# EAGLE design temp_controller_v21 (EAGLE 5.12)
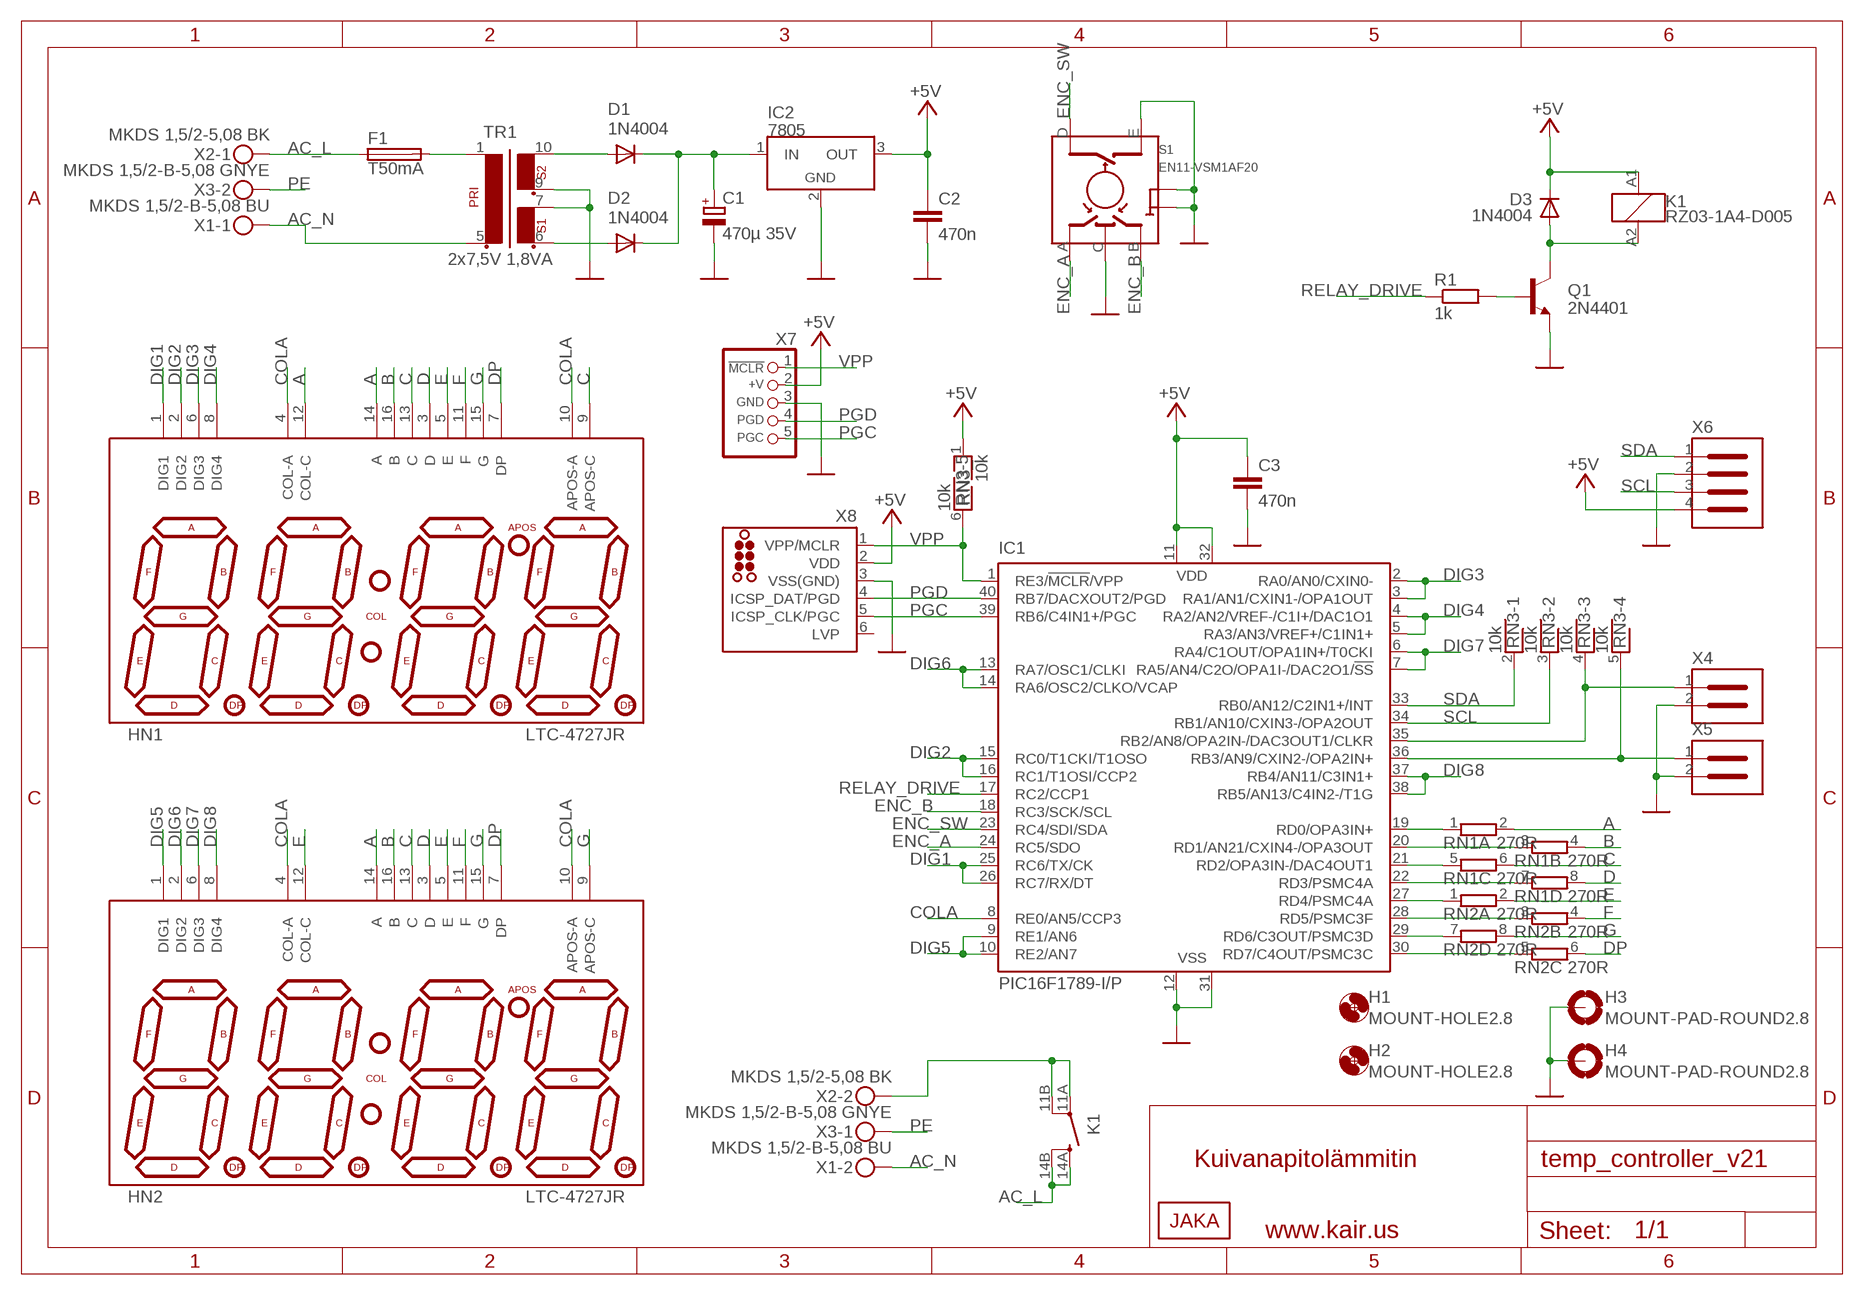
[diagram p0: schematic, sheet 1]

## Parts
C1  470µ 35V  CPOL-EUE5-13  [E5-13]
C2  470n  C-EU050-024X044  [C050-024X044]
C3  470n  C-EU050-024X044  [C050-024X044]
D1  1N4004  [DO41-10]
D2  1N4004  [DO41-10]
D3  1N4004  [DO41-10]
F1  T50mA  TR5  [TR5]
H1  MOUNT-HOLE2.8  [2,8]
H2  MOUNT-HOLE2.8  [2,8]
H3  MOUNT-PAD-ROUND2.8  [2,8-PAD]
H4  MOUNT-PAD-ROUND2.8  [2,8-PAD]
HN1  LTC-4727JR  7-SEGMENT-4DIGIT-YOUNGSUN  [7-SEGMENT-4DIGIT-YOUNGSUN]
HN2  LTC-4727JR  7-SEGMENT-4DIGIT-YOUNGSUN  [7-SEGMENT-4DIGIT-YOUNGSUN]
IC1  PIC16F1789-I/P  [DIL40]
IC2  7805  7805V  [TO220V]
K1  RZ03-1A4-D005  RT33K012  [RT-N/O16A5]
Q1  2N4401  2N4401-NPN-TO92-EBC  [TO92-EBC]
R1  1k  R-EU_0207/10  [0207/10]
RN1  270R  E4R  [SIL8]
RN2  270R  E4R  [SIL8]
RN3  10k  RNX5  [RN-6]
S1  EN11-VSM1AF20  [EN11-VSXXAXXX]
TR1  2x7,5V 1,8VA  EI30-2  [EI30-2]
U$1  JAKA_LOGO_SILK_NANO  [JAKA_SILK_NANO]
X1  MKDS 1,5/2-B-5,08 BU  MKDS1,5/2-B-5,08  [MKDS1,5/2-B-5,08]
X2  MKDS 1,5/2-5,08 BK  MKDS1,5/2-5,08  [MKDS1,5/2-5,08]
X3  MKDS 1,5/2-B-5,08 GNYE  MKDS1,5/2-B-5,08  [MKDS1,5/2-B-5,08]
X4  B2B-XH-A(LF)(SN)  [B2B-XH-A]
X5  B2B-XH-A(LF)(SN)  [B2B-XH-A]
X6  B4B-XH-A(LF)(SN)  [B4B-XH-A]
X7  CON_HEADER_PRG_PIC_ICSPB  [HEADER_PRG_1X05_ICSP_B]
X8  TC2030-MCP-NL-JKA  [TC2030-MCP-NL-JKA]

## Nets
+5V [supply]: C2.1 C3.1 D3.C IC1.11(VDD) IC1.32(VDD) IC2.3(OUT) K1.A1 RN3.1 X6.4 X7.2(+V) X8.2(VDD)
A: HN1.12(COL-C) HN1.14(A) HN2.14(A) RN1.2
AC_L [ac]: F1.1 K1.14A(2:SA) K1.14B(2:SB) X2.1
AC_N [ac]: TR1.5 X1.1 X1.2
B: HN1.16(B) HN2.16(B) RN1.4
C: HN1.9(APOS-C) HN1.13(C) HN2.13(C) RN1.6
COLA: HN1.4(COL-A) HN1.10(APOS-A) HN2.4(COL-A) HN2.10(APOS-A) IC1.8(RE0/AN5/CCP3)
D: HN1.3(D) HN2.3(D) RN1.8
DIG1: HN1.1(DIG1) IC1.25(RC6/TX/CK) IC1.26(RC7/RX/DT)
DIG2: HN1.2(DIG2) IC1.15(RC0/T1CKI/T1OSO) IC1.16(RC1/T1OSI/CCP2)
DIG3: HN1.6(DIG3) IC1.2(RA0/AN0/CXIN0-) IC1.3(RA1/AN1/CXIN1-/OPA1OUT)
DIG4: HN1.8(DIG4) IC1.4(RA2/AN2/VREF-/C1I+/DAC1O1) IC1.5(RA3/AN3/VREF+/C1IN1+)
DIG5: HN2.1(DIG1) IC1.9(RE1/AN6) IC1.10(RE2/AN7)
DIG6: HN2.2(DIG2) IC1.13(RA7/OSC1/CLKI) IC1.14(RA6/OSC2/CLKO/VCAP)
DIG7: HN2.6(DIG3) IC1.6(RA4/C1OUT/OPA1IN+/T0CKI) IC1.7(RA5/AN4/C2O/OPA1I-/DAC2O1/!SS!)
DIG8: HN2.8(DIG4) IC1.37(RB4/AN11/C3IN1+) IC1.38(RB5/AN13/C4IN2-/T1G)
DP: HN1.7(DP) HN2.7(DP) RN2.6
E: HN1.5(E) HN2.5(E) HN2.12(COL-C) RN2.2
ENC_A: IC1.24(RC5/SDO) S1.A
ENC_B: IC1.18(RC3/SCK/SCL) S1.B
ENC_SW: IC1.23(RC4/SDI/SDA) S1.D
F: HN1.11(F) HN2.11(F) RN2.4
G: HN1.15(G) HN2.9(APOS-C) HN2.15(G) RN2.8
GND [supply]: C1.- C2.2 C3.2 H3.B2,8(MOUNT) H4.B2,8(MOUNT) IC1.12(VSS) IC1.31(VSS) IC2.2(GND) Q1.E S1.C S1.E S1.GND1(GND) S1.GND2(GND) TR1.7 TR1.9 X4.2 X5.2 X6.2 X7.3(GND) X8.3(VSS(GND))
LOAD [ac]: K1.11A(2:PA) K1.11B(2:PB) X2.2
N$1: IC1.19(RD0/OPA3IN+) RN1.1
N$2: IC1.20(RD1/AN21/CXIN4-/OPA3OUT) RN1.3
N$3 [supply]: D2.A TR1.6
N$4 [supply]: D1.A TR1.10
N$5: IC1.21(RD2/OPA3IN-/DAC4OUT1) RN1.5
N$6: IC1.22(RD3/PSMC4A) RN1.7
N$7: IC1.27(RD4/PSMC4A) RN2.1
N$8: IC1.28(RD5/PSMC3F) RN2.3
N$9: IC1.29(RD6/C3OUT/PSMC3D) RN2.7
N$10: IC1.30(RD7/C4OUT/PSMC3C) RN2.5
N$11: Q1.B R1.2
N$12 [supply]: D3.A K1.A2 Q1.C
N$13 [supply]: C1.+ D1.C D2.C IC2.1(IN)
N$14 [ac]: F1.2 TR1.1
N$20: IC1.35(RB2/AN8/OPA2IN-/DAC3OUT1/CLKR) RN3.4 X4.1
N$21: IC1.36(RB3/AN9/CXIN2-/OPA2IN+) RN3.5 X5.1
PE [ac]: X3.1 X3.2
PGC: IC1.39(RB6/C4IN1+/PGC) X7.5(PGC) X8.5(ICSP_CLK/PGC)
PGD: IC1.40(RB7/DACXOUT2/PGD) X7.4(PGD) X8.4(ICSP_DAT/PGD)
RELAY_DRIVE: IC1.17(RC2/CCP1) R1.1
SCL: IC1.34(RB1/AN10/CXIN3-/OPA2OUT) RN3.3 X6.3
SDA: IC1.33(RB0/AN12/C2IN1+/INT) RN3.2 X6.1
VPP: IC1.1(RE3/!MCLR!/VPP) RN3.6 X7.1(/MCLR) X8.1(VPP/MCLR)
Unconnected: X8.6(LVP)

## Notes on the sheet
- Kuivanapitolämmitin
- www.kair.us

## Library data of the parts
C1 = omat:CPOL-EU: POLARIZED CAPACITOR, European symbol
C2 C3 = dual_atari:C-EU: CAPACITOR, European symbol
D1-D3 = omat:1N4004: DIODE
F1 = omat:TR5: FUSE; OC_FARNELL: unknown; OC_NEWARK: unknown
H1 H2 = dual_atari:MOUNT-HOLE: MOUNTING HOLE with drill center marker
H3 H4 = dual_atari:MOUNT-PAD-ROUND: MOUNTING PAD, round
HN1 HN2 = omat:7-SEGMENT-4DIGIT-YOUNGSUN: This is a part for the 4-Digit 7-segment LEDs from Young Sun. Different from the Digikey LEDs, all 16 pins are used. The LONGPADS Variant is used for a test jig, but you may like it because there is more pad to solder to. If you are concerned about routing space, the standard works just fine though.
IC1 = omat:PIC16F1789
IC2 = omat:7805
K1 = omat:RT33*: Power PCB Relay Inrush SCHRACK 1 pole 16 A, for inrush peak currents up to 80 A Source: http://www.schrack.com/.. 5825.pdf; MPN: RT33K012; OC_FARNELL: unknown; OC_NEWARK: 48M7964
Q1 = omat:*-NPN-: NPN Transistror
R1 = dual_atari:R-EU_: RESISTOR, European symbol
RN1 RN2 = omat:E4R: SIL RESISTOR; OC_FARNELL: unknown; OC_NEWARK: unknown
RN3 = dual_atari:RNX5: RESISTOR NETWORK; OC_FARNELL: unknown; OC_NEWARK: unknown
S1 = omat:EN11-VSM1AF20
TR1 = omat:EI30-2: TRANSFORMER 1 primary winding, 2 secondary windings ERA
U$1 = dual_atari:JAKA_LOGO
X1 X3 = omat:MKDS1,5/2: MKDS 1,5/ 2-5,08 Printklemme; MPN: MKDS 1,5/2-5.08
X2 = omat:MKDS1,5/2: MKDS 1,5/ 2-5,08 Printklemme
X4 X5 = omat:B2B-XH-A(LF)(SN)
X6 = omat:B4B-XH-A(LF)(SN)
X7 = omat:CON_HEADER_PRG_PIC_ICSP: 5-pin PIC In Circuit Serial Programming header
X8 = dual_atari:TC2030: TAG-CONNECT ISP Connector Manufacturer: Tag-Connect Cable for easy In-Circuit PCB Programming. Designed for Microchip ICD2, suitable for many others. Two variants - one "with legs" (for hads-free fit on PCB) and another "without legs" for quick programming. PADDescription 1MCLR/Vpp 2Vdd 3GND 4PGD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

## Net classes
0 default: width 0.3 mm, drill 0.7 mm, clearance 0.3 mm
1 supply: width 1 mm, drill 0.7 mm, clearance 0.3 mm to class 0, clearance 0.3 mm
2 ac: width 2 mm, drill 0.7 mm, clearance 8 mm to class 0, clearance 7 mm to class 1, clearance 2 mm

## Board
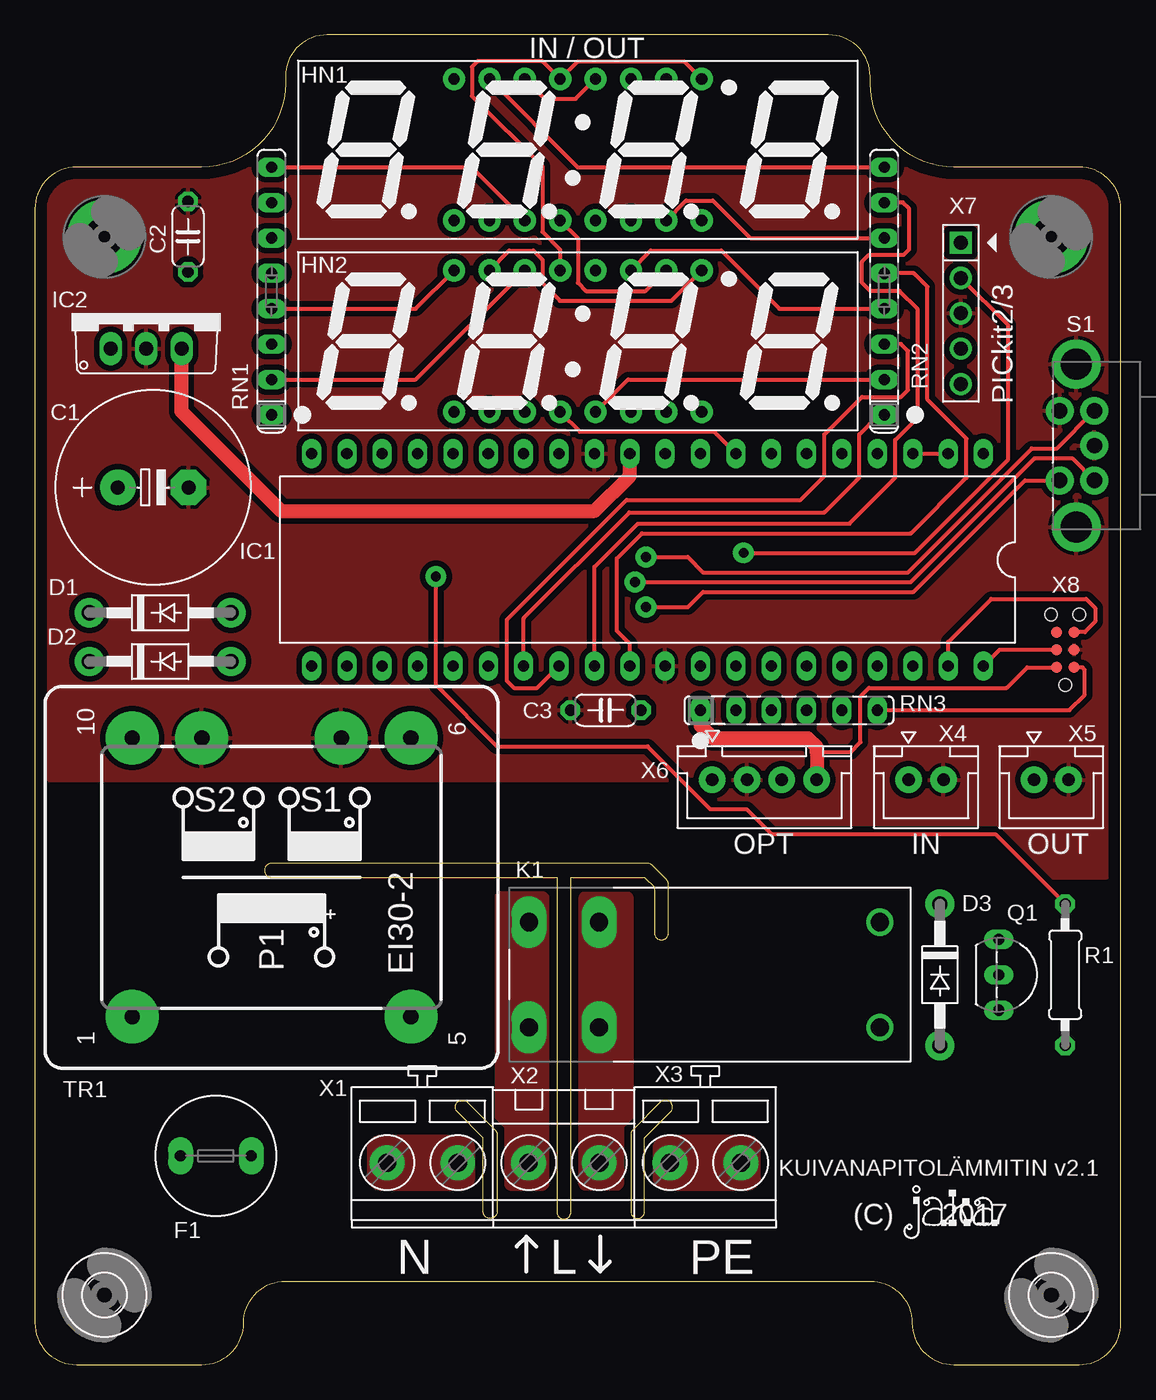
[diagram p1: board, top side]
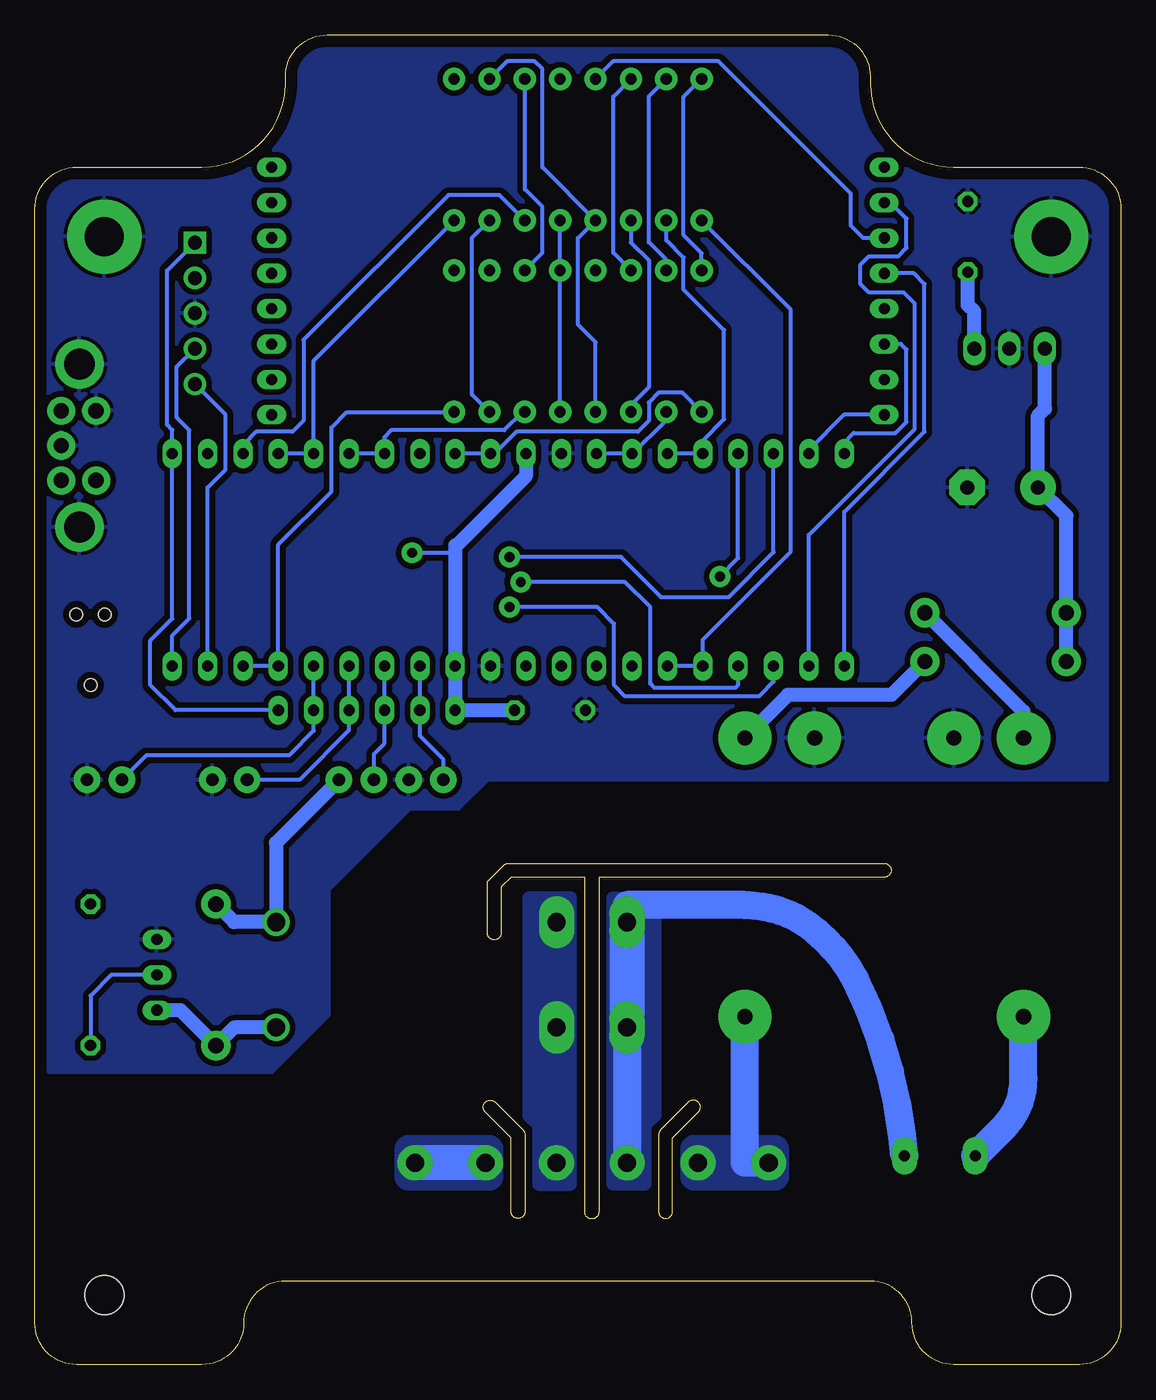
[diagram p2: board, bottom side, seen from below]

Size 78 x 95.5 mm. Coordinates in mm from the lower left corner, seen from the top.
Outline: 75,0 arc90 78,3 78,83 arc90 75,86 66,86 arc-90 60,92 60,92.5 arc90 57,95.5 21,95.5 arc90 18,92.5 18,92 arc-90 12,86 3,86 arc90 0,83 0,3 arc90 3,0 12,0 arc90 15,3 arc-90 18,6 60,6 arc-90 63,3 arc90 66,0 75,0
Copper layers (1*16): Top 0.035mm / dielectric 1.5mm / Bottom 0.035mm
Design rules "ITEADstudio_DRC *": minimum track width 0.3mm, minimum drill 0.7mm, track to track 0.3mm, track to pad 0.3mm, pad to pad 0.3mm, via to via 0.3mm, smd to smd 0mil, copper to edge 0.5mm, drill to drill 1mm, minimum pad ring 0.3mm, minimum via ring 0.3mm, stop-mask expansion 2mil, vias tented up to drill 100mil, thermal gap 10mil
bKeepout: area 68,76 to 78,86; area 0,76 to 10,86; area 0,0 to 10,10; area 68,0 to 78,10
Milling: 30 lines

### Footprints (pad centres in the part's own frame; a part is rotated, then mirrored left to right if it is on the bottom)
E5-13 = drill 1 pad 2.54 round: + -2.54,0 | drill 1 pad 2.54 octagon: - 2.54,0
C050-024X044 = drill 0.8 octagon: 1 -2.54,0; 2 2.54,0
DO41-10 = drill 1.1 pad 2.1 round: A 5.08,0; C -5.08,0
TR5 = drill 0.8 pad 1.778 long: 1 -2.54,0; 2 2.54,0
2,8 = hole 2.8: 0,0
2,8-PAD = drill 2.8 pad 5.334 round: B2,8 0,0
7-SEGMENT-4DIGIT-YOUNGSUN = drill 0.8 pad 1.6 round: 1 -8.89,-5.08; 2 -6.35,-5.08; 3 -3.81,-5.08; 4 -1.27,-5.08; 5 1.27,-5.08; 6 3.81,-5.08; 7 6.35,-5.08; 8 8.89,-5.08; 9 8.89,5.08; 10 6.35,5.08; 11 3.81,5.08; 12 1.27,5.08; 13 -1.27,5.08; 14 -3.81,5.08; 15 -6.35,5.08; 16 -8.89,5.08
DIL40 = drill 0.8 long: 1 -24.13,-7.62; 2 -21.59,-7.62; 3 -19.05,-7.62; 4 -16.51,-7.62; 5 -13.97,-7.62; 6 -11.43,-7.62; 7 -8.89,-7.62; 8 -6.35,-7.62; 9 -3.81,-7.62; 10 -1.27,-7.62; 11 1.27,-7.62; 12 3.81,-7.62; 13 6.35,-7.62; 14 8.89,-7.62; 15 11.43,-7.62; 16 13.97,-7.62; 17 16.51,-7.62; 18 19.05,-7.62; 19 21.59,-7.62; 20 24.13,-7.62; 21 24.13,7.62; 22 21.59,7.62; 23 19.05,7.62; 24 16.51,7.62; 25 13.97,7.62; 26 11.43,7.62; 27 8.89,7.62; 28 6.35,7.62; 29 3.81,7.62; 30 1.27,7.62; 31 -1.27,7.62; 32 -3.81,7.62; 33 -6.35,7.62; 34 -8.89,7.62; 35 -11.43,7.62; 36 -13.97,7.62; 37 -16.51,7.62; 38 -19.05,7.62; 39 -21.59,7.62; 40 -24.13,7.62
TO220V = drill 1 long: 1 -2.54,-2.54; 2 0,-2.54; 3 2.54,-2.54
RT-N/O16A5 = drill 1.3 pad 2.5 long: 11A 7.56,3.78; 11B 7.56,-3.78; 14A 12.6,3.78; 14B 12.6,-3.78 | drill 1.3 round: A1 -12.6,-3.78; A2 -12.6,3.78
TO92-EBC = drill 0.8 long: B 0,-1.27; C 2.54,-1.27; E -2.54,-1.27
0207/10 = drill 0.8 octagon: 1 -5.08,0; 2 5.08,0
SIL8 = drill 0.8 long: 1 -8.89,0; 2 -6.35,0; 3 -3.81,0; 4 -1.27,0; 5 1.27,0; 6 3.81,0; 7 6.35,0; 8 8.89,0
RN-6 = drill 0.8 long: 1 -6.35,0; 2 -3.81,0; 3 -1.27,0; 4 1.27,0; 5 3.81,0; 6 6.35,0
EN11-VSXXAXXX = drill 1.1 pad 2 round: A 1.3,-2.5; B 1.3,2.5; C 1.3,0; D -1.2,-2.5; E -1.2,2.5 | drill 2.2 pad 3.5 round: GND1 0,5.85; GND2 0,-5.85
EI30-2 = drill 1.1 pad 3.81 round: 1 -10.008,10.008; 5 -10.008,-10.008; 6 10.008,-10.008; 7 10.008,-5.004; 9 10.008,5.004; 10 10.008,10.008
MKDS1,5/2-B-5,08 = drill 1.3 pad 2.5 round: 1 -2.54,0; 2 2.54,0
MKDS1,5/2-5,08 = drill 1.3 pad 2.5 round: 1 -2.54,0; 2 2.54,0
B2B-XH-A = drill 0.9 pad 1.9 round: 1 -1.25,0; 2 1.25,0
B4B-XH-A = drill 0.9 pad 1.9 round: 1 -3.75,0; 2 -1.25,0; 3 1.25,0; 4 3.75,0
HEADER_PRG_1X05_ICSP_B = drill 1 square: 1 -5.08,0 | drill 1 round: 2 -2.54,0; 3 0,0; 4 2.54,0; 5 5.08,0
TC2030-MCP-NL-JKA = smd 0.787 x 0.787: 1 1.27,-0.635; 2 1.27,0.635; 3 2.54,-0.635; 4 2.54,0.635; 5 3.81,-0.635; 6 3.81,0.635 | hole 0.9: 0,0; 5.08,-1.016; 5.08,1.016

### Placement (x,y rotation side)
C1  8.5,63 0 top
C2  11,81 90 top
C3  41,47 180 top
D1  9,54 0 top
D2  9,50.5 0 top
D3  65,28 270 top
F1  13,15 180 top
H1  5,5 0 top
H2  73,5 0 top
H3  73,81 0 top
H4  5,81 0 top
HN1  39,87.25 0 top
HN2  39,73.5 0 top
IC1  44,57.8 180 top
IC2  8,75.5 0 top
K1  48.08,28 180 top
Q1  70.5,28 270 top
R1  74,28 270 top
RN1  17,77.1 90 top
RN2  61,77.1 90 top
RN3  54.16,47 0 top
S1  74.8,66 0 top
TR1  17,35 90 top
U$1  65.75,10.95 0 top
X1  27.84,14.5 0 top
X2  38,14.5 0 top
X3  48.16,14.5 0 top
X4  64,42 0 top
X5  73,42 0 top
X6  52.4,42 0 top
X7  66.5,75.5 270 top
X8  74,48.8 90 top

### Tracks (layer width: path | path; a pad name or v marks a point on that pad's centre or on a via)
+5V  (via drill 0.7 pad 1.5)
  Top 0.3: 56.15,44 58.6,44 59.3,44.7 59.3,48 59.9,48.6 69.8,48.6 71.27,50.07 X8.2 | v50.9,58.3 63.2,58.3 69.9,65 69.9,74.64 X7.2
  Top 1: IC1.11 42.73,63.83 40.2,61.3 17.7,61.3 10.54,68.46 IC2.3 | RN3.1 47.81,45.89 48.7,45 55.5,45 56.15,44.35 56.15,44 X6.4
  Bottom 0.3: v50.9,58.3 48.01,58.3 47.81,58.1
  Bottom 1: 42.73,64.92 IC1.11 42.73,63.83 47.72,58.84 47.81,58.84 47.81,58.1 IC1.32 RN3.1 C3.1 | IC2.3 10.54,75.64 11,76.1 C2.1 | X6.4 60.68,37.47 K1.A1 63.7,31.78 D3.C
A
  Top 0.3: HN1.12 38.84,90.9 36.62,90.9 HN1.14 | RN1.2 27.36,70.75 HN2.14
  Bottom 0.3: HN1.14 36.45,91.07 36.45,79.84 HN2.14
AC_L
  Bottom 2: F1.1 15.7,16.4 arc-20 19.1,27.7 arc-32 23.3,32.1 arc-24 27,33 35.48,33 K1.14B | K1.14A 35.46,24.22 X2.1
  Bottom 2.5: K1.14B K1.14A
  pour Top (no thermals): 34.2,12.75 36.45,12.75 arc90 36.7,13 36.7,33.5 arc90 36.45,33.75 33.5,33.75 arc90 33.25,33.5 33.25,17.8 33.95,17.1 33.95,13 arc90
  pour Bottom (no thermals): 34.2,12.75 36.45,12.75 arc90 36.7,13 36.7,33.5 arc90 36.45,33.75 33.5,33.75 arc90 33.25,33.5 33.25,17.8 33.95,17.1 33.95,13 arc90
AC_N
  Bottom 2: TR1.5 27.01,14.5 X1.1
  pour Bottom (no thermals): 24.09,13.5 arc90 24.84,12.75 30.64,12.75 arc90 31.39,13.5 31.39,15.5 arc90 30.64,16.25 24.84,16.25 arc90 24.09,15.5
  pour Top (no thermals): 24.09,13.5 arc90 24.84,12.75 30.64,12.75 arc90 31.39,13.5 31.39,15.5 arc90 30.64,16.25 24.84,16.25 arc90 24.09,15.5
B
  Top 0.3: RN1.4 27.36,75.83 HN2.16
  Bottom 0.3: HN1.16 31.4,91.04 31.4,81.1 30.11,79.81 HN2.16
C
  Top 0.3: HN2.13 37.73,80.07 36.45,81.35 36.45,86.05 31.4,91.1 31.4,93.2 31.8,93.6 36.46,93.6 HN1.13 39,93.6 46.62,93.6 HN1.9
  Bottom 0.3: HN1.13 36.46,93.6 28.9,93.6 19.4,84.1 19.4,81.8 18.51,80.91 RN1.6
COLA
  Top 0.3: HN2.10 43.87,77.1 39.6,77.1 39,77.7 39,80.9 HN1.4 | HN2.4 39.15,67 48.77,67 IC1.8
  Bottom 0.3: HN1.10 44.08,93.6 42.1,93.6 41.55,93.05 41.55,85.99 HN1.4 39,80.9 39,74.7 37.73,73.43 HN2.4
D
  Top 0.3: RN1.8 31.37,85.99 HN1.3
  Bottom 0.3: HN2.3 35.19,68.91 33.9,70.2 33.9,79.3 35.19,80.59 HN1.3
DIG1
  Bottom 0.3: IC1.26 IC1.25 30.03,52.07 23.7,58.4 23.7,75.76 HN1.1
DIG2
  Bottom 0.3: IC1.15 IC1.16 30.03,66.37 28.5,67.9 28.5,74.3 31.4,77.2 31.4,79.5 32.65,80.75 HN1.2
DIG3
  Top 0.3: IC1.3 IC1.2
  Bottom 0.3: IC1.3 63.05,66.05 62.1,67 59.5,67 58.7,67.8 58.7,73.6 48.3,84 44.64,84 HN1.6
DIG4
  Bottom 0.3: HN1.8 57.97,72.09 IC1.5 IC1.4
DIG5
  Bottom 0.3: HN2.1 31.49,69.8 33.2,69.8 33.9,69.1 33.9,67.8 34.7,67 43.4,67 44.98,65.42 IC1.10 IC1.9
DIG6
  Bottom 0.3: HN2.2 32.65,67.85 35.11,65.39 IC1.14 IC1.13
DIG7
  Bottom 0.3: IC1.6 IC1.7 52.89,66.61 52.4,67.1 44.3,67.1 42.98,68.42 HN2.6
DIG8
  Bottom 0.3: HN2.8 47.91,68.4 55.6,68.4 56.7,67.3 56.7,62.7 60.51,58.89 IC1.37 IC1.38
DP
  Top 0.3: HN1.7 46.78,83.6 48.7,83.6 51.39,80.91 RN2.6
  Bottom 0.3: HN1.7 46.6,80.92 46.6,69.67 HN2.7
E
  Top 0.3: RN2.2 42.6,70.75 HN2.5
  Bottom 0.3: HN1.5 HN2.12 HN2.5
ENC_A  (via drill 0.7 pad 1.5)
  Top 0.3: v43.1,56.2 62.9,56.2 71.8,65.1 74.5,65.1 S1.A
  Bottom 0.3: IC1.24 27.49,48.81 27.7,48.6 33.5,48.6 33.8,48.9 33.8,54.4 35.6,56.2 v43.1,56.2
ENC_B  (via drill 0.7 pad 1.5)
  Top 0.3: v43.9,58 46.9,58 48,56.9 62.7,56.9 71.6,65.8 73.4,65.8 S1.B
  Bottom 0.3: IC1.18 24.95,58.35 28.2,55.1 33,55.1 35.9,58 v43.9,58
ENC_SW  (via drill 0.7 pad 1.5)
  Top 0.3: v43.9,54.4 46.9,54.4 48,55.5 63.1,55.5 71.1,63.5 S1.D
  Bottom 0.3: IC1.23 24.95,49.05 26,48 35.6,48 36.4,48.8 36.4,53.2 37.6,54.4 v43.9,54.4
F
  Top 0.3: RN2.4 53.47,75.83 49.3,80 44.23,80 HN2.11
  Bottom 0.3: HN1.11 42.81,84.41 41.55,83.15 41.55,79.84 HN2.11
G
  Top 0.3: HN2.9 45.71,76.4 37.7,76.4 36.45,77.65 36.45,79.35 35.8,80 34.07,80 HN2.15 | RN2.8 38.99,85.99 HN1.15
  Bottom 0.3: HN1.15 33.9,91.08 33.9,80.6 32.65,79.35 HN2.15
GND
  pour Bottom (isolate 0.4): 1,42 45.5,42 47.6,39.9 51.1,39.9 56.9,34.1 56.9,25.1 61,21 77,21 77,83 arc90 75,85 66,85 arc-90 59,92 59,92.5 arc90 57,94.5 21,94.5 arc90 19,92.5 19,92 arc-90 12,85 3,85 arc90 1,83
  pour Top (isolate 0.4): 1,42 45.5,42 47.6,39.9 51.1,39.9 56,35 77,35 77,83 arc90 75,85 66,85 arc-90 59,92 59,92.5 arc90 57,94.5 21,94.5 arc90 19,92.5 19,92 arc-90 12,85 3,85 arc90 1,83
LOAD
  pour Bottom (no thermals): 41.8,12.75 39.55,12.75 arc-90 39.3,13 39.3,33.5 arc-90 39.55,33.75 42.5,33.75 arc-90 42.75,33.5 42.75,17.8 42.05,17.1 42.05,13 arc-90
  pour Top (no thermals): 41.8,12.75 39.55,12.75 arc-90 39.3,13 39.3,33.5 arc-90 39.55,33.75 42.5,33.75 arc-90 42.75,33.5 42.75,17.8 42.05,17.1 42.05,13 arc-90
N$1
  Bottom 0.3: RN1.1 19.89,68.21 22.41,65.69 IC1.19
N$2
  Bottom 0.3: IC1.20 19.87,66.23 19.2,66.9 16.2,66.9 15.4,67.7 15.4,72.9 15.79,73.29 RN1.3
N$3
  Bottom 1: D2.A 16.48,48.1 23.91,48.1 TR1.6
N$4
  Bottom 1: D1.A 6.99,46.91 TR1.10
N$5
  Bottom 0.3: IC1.21 19.87,61.23 14.1,67 14.1,77.6 14.87,78.37 RN1.5
N$6
  Bottom 0.3: IC1.22 22.41,59.59 14.8,67.2 14.8,76.2 15.6,77 18.1,77 18.7,77.6 18.7,79 18.1,79.6 16,79.6 15.4,80.2 15.4,82.3 16.55,83.45 RN1.7
N$7
  Top 0.3: IC1.27 35.11,53.61 42.7,61.2 56.7,61.2 59.2,63.7 59.2,66.8 60.61,68.21 RN2.1
N$8
  Top 0.3: IC1.28 36.07,48.6 34.4,48.6 33.9,49.1 33.9,53.5 42.5,62.1 55,62.1 56.7,63.8 56.7,66.8 59.4,69.5 62.2,69.5 62.7,70 62.7,72.8 62.21,73.29 RN2.3
N$9
  Top 0.3: IC1.29 40.19,57.29 43.3,60.4 58.5,60.4 61.8,63.7 61.8,66.4 63.4,68 63.4,75.8 62.1,77.1 60,77.1 59.4,77.7 59.4,79.2 59.9,79.7 62.4,79.7 62.8,80.1 62.8,83 62.35,83.45 RN2.7
N$10
  Top 0.3: RN2.5 63.13,78.37 64.1,77.4 64.1,69.3 66.9,66.5 66.9,63.7 62.9,59.7 43.6,59.7 41.8,57.9 41.8,52.7 42.73,51.77 IC1.30
N$11
  Bottom 0.3: Q1.B 72.5,28 74,26.5 R1.2
N$12
  Bottom 1: Q1.C 67.54,25.46 D3.A 63.7,24.22 K1.A2
N$13
  Bottom 1: D2.C D1.C 3.92,60.96 C1.+ 5.96,68.14 5.46,68.64 IC2.1
N$14
  Bottom 2: F1.2 8.46,17 arc-45 6.99,20.54 TR1.1
N$20
  Bottom 0.3: IC1.35 RN3.4 55.43,45.57 59,42 X4.1
N$21
  Bottom 0.3: IC1.36 RN3.5 57.97,45.53 59.75,43.75 70,43.75 X5.1
PE
  Bottom 2.5: X3.1 X3.2
  pour Top (no thermals): 44.61,13.5 arc90 45.36,12.75 51.16,12.75 arc90 51.91,13.5 51.91,15.5 arc90 51.16,16.25 45.36,16.25 arc90 44.61,15.5
  pour Bottom (no thermals): 44.61,13.5 arc90 45.36,12.75 51.16,12.75 arc90 51.91,13.5 51.91,15.5 arc90 51.16,16.25 45.36,16.25 arc90 44.61,15.5
PGC
  Top 0.3: IC1.39 65.59,51.9 68.69,55 75.5,55 76.15,54.35 76.15,53.35 75.41,52.61 X8.5
  Bottom 0.3: IC1.39 65.59,62.99 64.3,64.28 64.3,68.22 X7.5
PGD
  Top 0.3: X8.4 69.29,51.34 IC1.40
  Bottom 0.3: IC1.40 68.13,52.37 66.9,53.6 66.9,67.1 67.8,68 67.8,71.66 X7.4
RELAY_DRIVE  (via drill 0.7 pad 1.5)
  Top 0.3: R1.1 68.98,38.1 52.9,38.1 51.1,39.9 48.5,39.9 44,44.4 33.2,44.4 28.8,48.8 v28.8,56.6
  Bottom 0.3: v28.8,56.6 27.49,57.91 IC1.17
SCL
  Bottom 0.3: IC1.34 RN3.3 52.89,44.61 53.65,43.85 X6.3
SDA
  Bottom 0.3: IC1.33 RN3.2 50.35,45.15 48.65,43.45 X6.1
VPP
  Top 0.3: RN3.6 74.3,47 75.4,48.1 75.4,49.9 75.23,50.07 X8.1
  Bottom 0.3: RN3.6 67.9,47 69.7,48.8 69.7,52 68.13,53.57 IC1.1 68.13,67.13 68.5,67.5 68.5,78.58 X7.1

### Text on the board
tPlace: PICkit2/3 | KUIVANAPITOLÄMMITIN v2.1 | (C) 2017 | N | L | PE
tNames: IN / OUT | OPT | IN | OUT
bStop: WWW.KAIR.US
_tsilk: IN / OUT | HN1 | X7 | C2 | 470n | HN2 | IC2 | 7805 | 270R | S1 | 270R | RN2 | RN1 | PICkit2/3 | C1 | PIC16F1789-I/P | 470µ 35V | IC1 | D1 | 1N4004 | X8 | D2 | 1N4004 | RN3 | 10k | C3 | 10 | 6 | X4 | X5 | 470n | X6 | S2 | S1 | OPT | IN | OUT | K1 | D3 | Q1 | P1 | R1 | RZ03-1A4-D005 | 1k | 2x7,5V 1,8VA | EI30-2 | 5 | 2N4401 | 1 | X2 | X3 | 1N4004 | TR1 | X1 | KUIVANAPITOLÄMMITIN v2.1 | (C) 2017 | F1 | T50mA | N | L | PE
